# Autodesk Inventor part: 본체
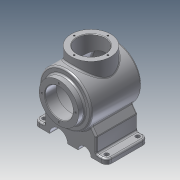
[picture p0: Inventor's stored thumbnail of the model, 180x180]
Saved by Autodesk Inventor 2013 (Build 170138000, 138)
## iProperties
Created: 2018-08
Part Number: 본체
Material: 알루미늄 6061
Document SubType Name: Modeling
Designer: Administrator
Density: 2.71 g/cm^3
Mass: 1884.26 g
Surface Area: 1092.03 cm^2
Volume: 695.298 cm^3
Author: Administrator
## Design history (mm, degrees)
sketch "스케치1"
  geometry: L1 (-50, 0)-(58, 0); L2 (-50, 0)-(-50, 50); L3 (-50, 50)-(46.671, 50); A1 r 116 centre (-58, 0) between (58, 0) and (46.671, 50); 1 further point
  constraints: 6 end point, 2 perpendicular, 2 point on circle, 1 centre point, 1 horizontal, 1 horizontal alignment, 1 point on line
  dimensions: "d0" = 108 distance of L1.start L1.end; "d1" = 50 distance of point (0, 0) L1.start; "d2" = 116 radius of A1; "d3" = 100 diameter of L3 L1
revolve "회전1" sketch "스케치1" stored, may be unused: angle "d4" = 90 deg
feature "쉘1" dims "d5" = 10
sketch "스케치2"
  geometry: C1 r 50 at (0, 0) reference; C2 r 38 at (0, 0)
  constraints: 1 centre point, 1 coincident
  dimensions: "d6" = 38 radius of C2
extrude "돌출1" join sketch "스케치2" distance "d7" = 12; taper "d8" = 0 deg
sketch "스케치3"
  geometry: C1 r 38 at (0, 0) reference; C2 r 27 at (0, 0)
  constraints: 1 centre point, 1 coincident
  dimensions: "d9" = 27 radius of C2
extrude "돌출2" cut sketch "스케치3" distance "d10" = 22; taper "d11" = 0 deg
sketch "스케치4"
  geometry: L1 (0, 0)-(0, 32.5); C1 r 38 at (0, 0) reference; 1 further point
  constraints: 2 end point, 1 coincident, 1 vertical
  dimensions: "d12" = 32.5 distance of L1.start L1.end
hole "구멍1" sketch "스케치4" at (0, 32.5) diameter "d13" = 3.242; stored, may be unused: countersink angle "d17" = 90 deg, drill point angle "d19" = 118 deg; dims "d14" = 8, "d15" = 4, "d16" = 2, "d18" = 10
node "작업 평면1"
sketch "스케치5"
  geometry: L1 (40, -70)-(-40, -70); L2 (-40, -70)-(-40, 70); L3 (-40, 70)-(40, 70); L4 (40, 70)-(40, -70); L5 (40, -70)-(-40, 70); L6 (-40, -70)-(40, 70); 1 further point
  constraints: 12 end point, 2 midpoint, 2 parallel, 1 horizontal, 1 perpendicular
  dimensions: "d24" = 80 distance of L2.end L3.end; "d25" = 140 distance of L1.end L2.end
extrude "돌출3" join sketch "스케치5" distance "d26" = 10; taper "d27" = 0 deg
node "작업 평면2"
sketch "스케치7"
  geometry: C1 r 38 at (0, 0); 1 further point
  constraints: 1 centre point, 1 coincident
  dimensions: "d34" = 38 radius of C1
extrude "돌출4" join sketch "스케치7" stored distance "d35" = 10; taper "d36" = 0 deg
sketch "스케치8"
  geometry: C1 r 38 at (0, 0) reference; C2 r 27 at (0, 0)
  constraints: 1 centre point, 1 coincident
  dimensions: "d37" = 27 radius of C2
extrude "돌출5" cut sketch "스케치8" distance "d38" = 70; taper "d39" = 0 deg
sketch "스케치9"
  geometry: L1 (0, 0)-(0, 32.5); C1 r 38 at (0, 0) reference; 1 further point
  constraints: 2 end point, 1 coincident, 1 vertical
  dimensions: "d40" = 32.5 distance of L1.start L1.end
hole "구멍2" sketch "스케치9" at (0, 32.5) diameter "d41" = 3.242; stored, may be unused: countersink angle "d45" = 90 deg, drill point angle "d47" = 118 deg; dims "d42" = 8, "d43" = 4, "d44" = 2, "d46" = 10
node "작업 평면3"
sketch "스케치10"
  geometry: C1 r 32.5 at (0, 0); 1 further point
  constraints: 1 centre point, 1 coincident, 1 other
  dimensions: "d52" = 32.5 radius of C1
feature "엠보싱1" sketch "스케치10" dims "d1" = 50, "d10" = 22, "d54" = 0.5, "d55" = 0
sketch "스케치11"
  geometry: L1 (-72, 70)-(-72, -70) reference; L2 (-82, -70)-(-72, -70) reference; L3 (-82, 70)-(-72, 70) reference; L4 (-72, -70)-(-29.59, -40.304); L5 (-72, 70)-(-29.59, 40.304); L6 (-43.437, -50)-(-72, -50); L7 (-43.437, 50)-(-72, 50); A1 r 50 centre (0, 0) between (-29.59, -40.304) and (-29.59, 40.304) reference; 1 further point
  constraints: 8 end point, 4 point on line, 2 perpendicular, 2 point on circle
  dimensions: "d62" = 35 deg angle of L2 L4; "d63" = 35 deg angle of L3 L5; "d64" = 20 distance between parallel lines of L2 L6; "d65" = 20 distance between parallel lines of L3 L7
extrude "돌출6" join sketch "스케치11" stored distance "d66" = 80; taper "d67" = 0 deg
fillet "모깎기1" dims "d75" = 10
sketch "스케치13"
  geometry: A1 r 10 centre (30, -60) between (30, -70) and (40, -60) reference; A2 r 10 centre (-30, -60) between (-40, -60) and (-30, -70) reference; 3 further points
  constraints: 2 coincident
hole "구멍3" sketch "스케치13" at (-30, -60), (30, -60) diameter "d76" = 8; stored, may be unused: countersink angle "d80" = 90 deg, drill point angle "d82" = 118 deg; dims "d77" = 8, "d78" = 4, "d79" = 2, "d81" = 10
sketch "스케치14"
  geometry: A1 r 10 centre (30, 60) between (40, 60) and (30, 70) reference; A2 r 10 centre (-30, 60) between (-30, 70) and (-40, 60) reference; 3 further points
  constraints: 2 coincident
hole "구멍4" sketch "스케치14" at (-30, 60), (30, 60) diameter "d83" = 8; stored, may be unused: countersink angle "d87" = 90 deg, drill point angle "d89" = 118 deg; dims "d84" = 8, "d85" = 4, "d86" = 2, "d88" = 10
fillet "모깎기2" dims "d90" = 3
fillet "모깎기3" dims "d91" = 3
fillet "모깎기5" dims "d93" = 3
fillet "모깎기8" dims "d96" = 3
fillet "모깎기9" dims "d97" = 3
fillet "모깎기10" dims "d98" = 3
fillet "모깎기11" dims "d99" = 3
chamfer "모따기1" distance "d100" = 1; stored, may be unused: second distance "d101" = 2, angle "d102" = 45 deg
fillet "모깎기12" dims "d103" = 3
sketch "스케치15"
  geometry: L1 (-82, -60)-(-82, 60) reference; C1 r 17.5 at (-82, -22.5); C2 r 12.5 at (-82, 27.5); 1 further point
  constraints: 2 centre point, 2 point on line
  dimensions: "d104" = 17.5 radius of C1; "d105" = 22.5 vertical distance of C1.centre point (0, 0); "d106" = 12.5 radius of C2; "d107" = 27.5 vertical distance of C2.centre point (0, 0)
extrude "돌출8" cut sketch "스케치15" stored distance "d108" = 80; taper "d109" = 0 deg
node "솔리드1"
pattern_circular "원형 패턴1" dims angle "d21" = 360 deg
pattern_circular "원형 패턴2" dims angle "d49" = 360 deg
other parameters: "d23" = -82, "d33" = 65
